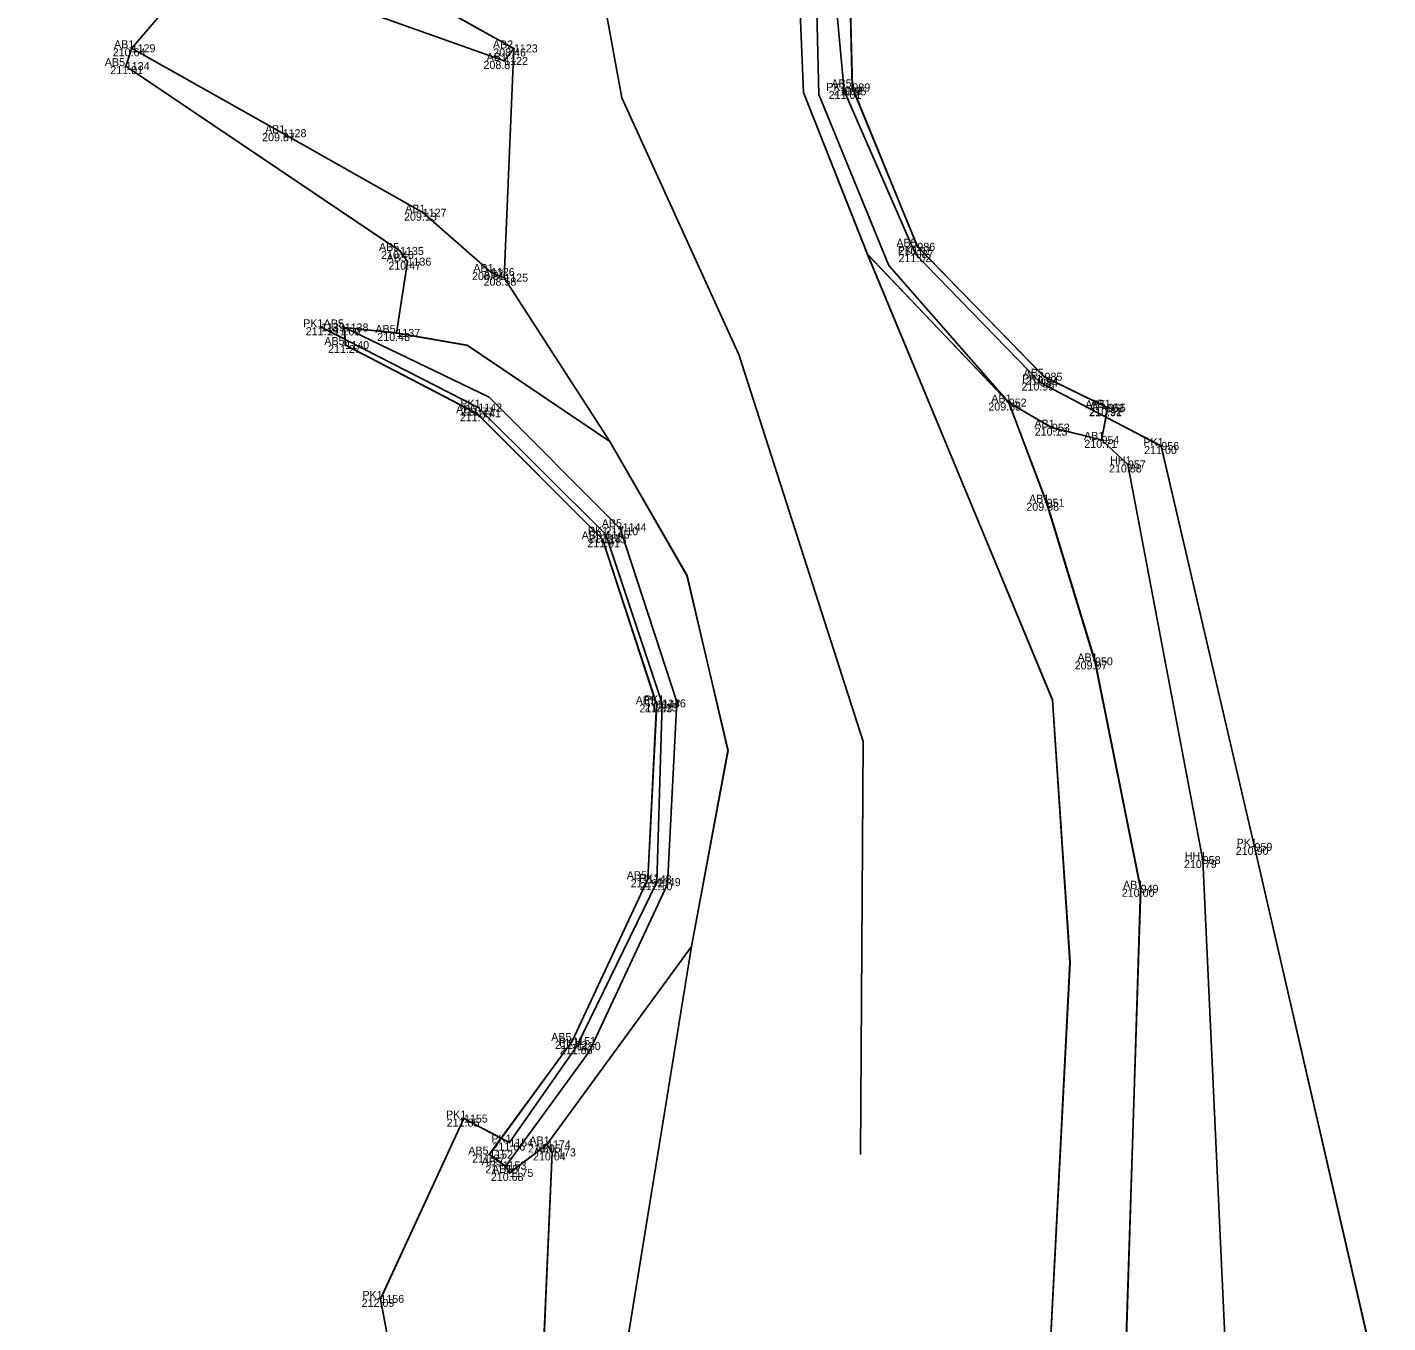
# Model space of a CAD drawing. Extents: x -262982 to -262706, y -1238714 to -1237093.
# Drawn here: x -262758.86 to -262724.86, y -1237246.95 to -1237214.58 of the extents above; entities that cross this region are included whole.
import ezdxf

# ---------------------------------------------------------------- set-up
doc = ezdxf.new("R2010")
doc.units = 0
for name, color, linetype in [('01_Hrana_betónu', 7, 'Continuous'), ('02_Oplotenie', 7, 'Continuous'), ('05_Hrana_terénu', 7, 'Continuous'), ('09_Múrik', 7, 'Continuous'), ('12_Prevzate', 7, 'Continuous'), ('Groma (21)', 7, 'Continuous'), ('Groma (22)', 7, 'Continuous'), ('Groma (23)', 7, 'Continuous'), ('Groma (24)', 7, 'Continuous'), ('U007_Betónové_dno', 7, 'Continuous'), ('U007_Betónový_múrik', 7, 'Continuous'), ('U007_Betóny_prídavné', 7, 'Continuous'), ('U007_Zeleň_vnútro', 7, 'Continuous')]:
    doc.layers.add(name, color=color, linetype=linetype)

msp = doc.modelspace()

# ---------------------------------------------------------------- linework, layer by layer
at = {"layer": '01_Hrana_betónu'}
msp.add_line((-262746.698, -1237215.108), (-262749.163, -1237213.734), dxfattribs=at)
for points in [[(-262756.251, -1237215.104), (-262752.477, -1237217.225), (-262748.975, -1237219.211), (-262747.271, -1237220.695), (-262746.938, -1237220.836), (-262746.698, -1237215.108), (-262746.941, -1237215.42), (-262750.811, -1237214.043), (-262751.454, -1237213.873), (-262753.276, -1237211.819), (-262753.562, -1237211.959)], [(-262734.328, -1237223.957), (-262733.383, -1237226.46), (-262732.174, -1237230.423), (-262731.033, -1237236.107), (-262731.406, -1237247.829), (-262731.217, -1237250.422), (-262730.427, -1237258.013), (-262730.707, -1237262.398)], [(-262745.779, -1237255.161), (-262745.901, -1237254.131), (-262746.066, -1237250.172), (-262745.744, -1237242.694), (-262745.872, -1237242.495), (-262746.806, -1237243.207), (-262746.909, -1237243.042)]]:
    msp.add_lwpolyline(points, dxfattribs=at)
at = {"layer": '02_Oplotenie'}
for points in [[(-262738.713, -1237213.277), (-262738.443, -1237216.169), (-262736.656, -1237220.248), (-262733.547, -1237223.456), (-262730.516, -1237225.043), (-262728.187, -1237235.058), (-262724.856, -1237249.517), (-262728.33, -1237250.897), (-262727.224, -1237257.246), (-262729.793, -1237261.019), (-262730.23, -1237281.105)], [(-262745.291, -1237290.168), (-262746.451, -1237287.071), (-262746.711, -1237279.427), (-262746.875, -1237275.982), (-262747.173, -1237269.439), (-262747.831, -1237258.131), (-262750.035, -1237246.355), (-262747.946, -1237241.849), (-262746.811, -1237242.447), (-262745.123, -1237240.039), (-262743.124, -1237235.94), (-262742.995, -1237231.474), (-262744.402, -1237227.257), (-262747.587, -1237224.08), (-262751.517, -1237222.073)]]:
    msp.add_lwpolyline(points, dxfattribs=at)
at = {"layer": '05_Hrana_terénu'}
msp.add_lwpolyline([(-262732.01, -1237224.888), (-262731.351, -1237225.503), (-262729.482, -1237235.388), (-262728.873, -1237248.563), (-262728.752, -1237252.453), (-262727.648, -1237257.282)], dxfattribs=at)
at = {"layer": '09_Múrik'}
for points in [[(-262732.01, -1237224.888), (-262733.251, -1237224.584), (-262734.328, -1237223.957), (-262737.33, -1237220.535), (-262739.076, -1237216.256), (-262739.151, -1237213.155), (-262738.631, -1237208.399), (-262738.385, -1237205.844), (-262736.697, -1237205.453), (-262737.25, -1237205.51), (-262738.513, -1237205.639)], [(-262732.01, -1237224.888), (-262731.851, -1237224.086), (-262733.435, -1237223.311), (-262736.613, -1237220.064), (-262738.238, -1237216.081), (-262738.308, -1237213.191), (-262737.794, -1237208.485), (-262737.605, -1237206.527), (-262736.507, -1237206.273), (-262736.697, -1237205.453)], [(-262750.927, -1237222.08), (-262749.634, -1237222.217), (-262749.356, -1237220.435), (-262749.544, -1237220.169), (-262756.398, -1237215.55)], [(-262746.909, -1237243.042), (-262744.809, -1237240.166), (-262742.858, -1237235.99), (-262742.624, -1237231.431), (-262744.042, -1237227.104), (-262747.319, -1237223.818), (-262750.927, -1237222.08)], [(-262746.909, -1237243.042), (-262747.313, -1237242.747), (-262745.241, -1237239.91), (-262743.352, -1237235.867), (-262743.128, -1237231.498), (-262744.48, -1237227.373), (-262747.618, -1237224.226), (-262750.911, -1237222.518), (-262750.927, -1237222.08)]]:
    msp.add_lwpolyline(points, dxfattribs=at)
at = {"layer": '12_Prevzate'}
for p, q in [((-262746.938, -1237220.836), (-262744.296, -1237224.926)), ((-262743.883, -1237247.547), (-262742.258, -1237237.55))]:
    msp.add_line(p, q, dxfattribs=at)
for points in [[(-262791.497, -1237120.005), (-262786.858, -1237124.868), (-262784.379, -1237126.547), (-262780.632, -1237128.447), (-262776.424, -1237129.031), (-262770.683, -1237129.062), (-262763.851, -1237132.452), (-262760.164, -1237141.037), (-262754.722, -1237164.802), (-262750.179, -1237185.786), (-262745.67, -1237207.188), (-262744.002, -1237216.34), (-262741.077, -1237222.757), (-262737.968, -1237232.423), (-262738.038, -1237242.742)], [(-262734.328, -1237223.957), (-262737.856, -1237220.253), (-262739.459, -1237216.209), (-262739.61, -1237212.605), (-262739.376, -1237209.427), (-262739.154, -1237207.455), (-262738.963, -1237206.444), (-262738.513, -1237205.639)], [(-262733.43, -1237250.203), (-262732.797, -1237237.943), (-262733.238, -1237231.387), (-262737.856, -1237220.253)], [(-262745.872, -1237242.495), (-262742.258, -1237237.55), (-262741.346, -1237232.652), (-262742.372, -1237228.278), (-262744.296, -1237224.926), (-262747.864, -1237222.526), (-262749.634, -1237222.217)]]:
    msp.add_lwpolyline(points, dxfattribs=at)
at = {"layer": 'Groma (21)'}
for centre in [(-262756.251, -1237215.104), (-262746.698, -1237215.108), (-262756.398, -1237215.55), (-262746.941, -1237215.42), (-262738.443, -1237216.169), (-262738.238, -1237216.081), (-262752.477, -1237217.225), (-262748.975, -1237219.211), (-262736.613, -1237220.064), (-262749.544, -1237220.169), (-262749.356, -1237220.435), (-262736.656, -1237220.248), (-262747.271, -1237220.695), (-262746.938, -1237220.836), (-262751.517, -1237222.073), (-262750.927, -1237222.08), (-262750.911, -1237222.518), (-262749.634, -1237222.217), (-262733.547, -1237223.456), (-262733.435, -1237223.311), (-262747.587, -1237224.08), (-262734.328, -1237223.957), (-262731.892, -1237224.099), (-262731.851, -1237224.086), (-262747.618, -1237224.226), (-262733.251, -1237224.584), (-262732.01, -1237224.888), (-262730.516, -1237225.043), (-262731.351, -1237225.503), (-262733.383, -1237226.46), (-262744.402, -1237227.257), (-262743.978, -1237227.072), (-262744.48, -1237227.373), (-262732.174, -1237230.423), (-262743.128, -1237231.498), (-262742.995, -1237231.474), (-262728.187, -1237235.058), (-262729.482, -1237235.388), (-262743.352, -1237235.867), (-262743.124, -1237235.94), (-262731.033, -1237236.107), (-262745.241, -1237239.91), (-262745.123, -1237240.039), (-262747.946, -1237241.849), (-262746.811, -1237242.447), (-262745.872, -1237242.495), (-262747.313, -1237242.747), (-262745.744, -1237242.694), (-262746.981, -1237243.018), (-262746.806, -1237243.207), (-262750.035, -1237246.355)]:
    msp.add_circle(centre, 0.01, dxfattribs=at)
at = {"layer": 'U007_Betónové_dno'}
msp.add_lwpolyline([(-262739.61, -1237212.61), (-262739.46, -1237216.21), (-262737.86, -1237220.25), (-262733.24, -1237231.39), (-262732.8, -1237237.94), (-262733.43, -1237250.2), (-262737.11, -1237251.76), (-262738.71, -1237251.34), (-262743.88, -1237247.55), (-262742.26, -1237237.55), (-262741.35, -1237232.65), (-262742.37, -1237228.28), (-262744.3, -1237224.93), (-262746.94, -1237220.84), (-262746.7, -1237215.11), (-262749.16, -1237213.73)], dxfattribs=at)
at = {"layer": 'U007_Betónový_múrik'}
for points in [[(-262737.86, -1237220.25), (-262739.46, -1237216.21), (-262739.61, -1237212.61), (-262739.38, -1237209.43), (-262739.15, -1237207.46), (-262738.96, -1237206.44), (-262738.51, -1237205.64), (-262737.25, -1237205.51), (-262736.7, -1237205.45), (-262736.51, -1237206.27), (-262737.61, -1237206.53), (-262737.79, -1237208.49), (-262738.31, -1237213.19), (-262738.24, -1237216.08), (-262736.61, -1237220.06), (-262733.44, -1237223.31), (-262731.85, -1237224.09), (-262732.01, -1237224.89), (-262733.25, -1237224.58), (-262734.33, -1237223.96)], [(-262746.81, -1237243.21), (-262746.91, -1237243.04), (-262747.31, -1237242.75), (-262745.24, -1237239.91), (-262743.35, -1237235.87), (-262743.13, -1237231.5), (-262744.48, -1237227.37), (-262747.62, -1237224.23), (-262750.91, -1237222.52), (-262750.93, -1237222.08), (-262749.63, -1237222.22), (-262747.86, -1237222.53), (-262744.3, -1237224.93), (-262742.37, -1237228.28), (-262741.35, -1237232.65), (-262742.26, -1237237.55), (-262745.87, -1237242.5)]]:
    msp.add_lwpolyline(points, close=True, dxfattribs=at)
at = {"layer": 'U007_Betóny_prídavné'}
for points in [[(-262755.22, -1237185.8), (-262749.16, -1237213.73), (-262746.7, -1237215.11), (-262746.94, -1237220.84), (-262744.3, -1237224.93), (-262747.86, -1237222.53), (-262749.63, -1237222.22), (-262749.36, -1237220.44), (-262749.54, -1237220.17), (-262756.4, -1237215.55), (-262756.25, -1237215.1), (-262753.56, -1237211.96), (-262753.28, -1237211.82), (-262751.45, -1237213.87), (-262750.81, -1237214.04), (-262751.86, -1237211.25), (-262755.01, -1237196.17), (-262759.85, -1237174.71), (-262764.43, -1237153.07), (-262766.66, -1237143.6), (-262767.82, -1237142.01), (-262766.6, -1237139.24), (-262764.4, -1237144.52), (-262759.45, -1237166.49)], [(-262731.03, -1237236.11), (-262731.41, -1237247.83), (-262731.22, -1237250.42), (-262730.43, -1237258.01), (-262730.71, -1237262.4), (-262732.38, -1237264.31), (-262732.87, -1237254.98), (-262733.43, -1237250.2), (-262732.8, -1237237.94), (-262733.24, -1237231.39), (-262737.86, -1237220.25), (-262734.33, -1237223.96), (-262733.38, -1237226.46), (-262732.17, -1237230.42)], [(-262742.26, -1237237.55), (-262743.88, -1237247.55), (-262744.04, -1237249.13), (-262744.27, -1237251.41), (-262744.52, -1237254.38), (-262744.61, -1237256.32), (-262745.78, -1237255.16), (-262745.9, -1237254.13), (-262746.07, -1237250.17), (-262745.74, -1237242.69), (-262745.87, -1237242.5)]]:
    msp.add_lwpolyline(points, close=True, dxfattribs=at)
at = {"layer": 'U007_Zeleň_vnútro'}
for points in [[(-262733.25, -1237224.58), (-262732.01, -1237224.89), (-262731.9, -1237224.32), (-262730.52, -1237225.04), (-262728.19, -1237235.06), (-262724.86, -1237249.52), (-262728.33, -1237250.9), (-262727.23, -1237257.19), (-262727.65, -1237257.28), (-262730.71, -1237262.4), (-262730.43, -1237258.01), (-262731.22, -1237250.42), (-262731.41, -1237247.83), (-262731.03, -1237236.11), (-262732.17, -1237230.42), (-262733.38, -1237226.46), (-262734.33, -1237223.96)], [(-262746.07, -1237250.17), (-262745.9, -1237254.13), (-262745.78, -1237255.16), (-262747.83, -1237258.13), (-262750.03, -1237246.36), (-262747.95, -1237241.85), (-262747.02, -1237242.34), (-262747.31, -1237242.75), (-262746.91, -1237243.04), (-262746.81, -1237243.21), (-262745.87, -1237242.5), (-262745.74, -1237242.69)]]:
    msp.add_lwpolyline(points, close=True, dxfattribs=at)

# ---------------------------------------------------------------- texts
at = {"layer": 'Groma (22)'}
for s, p in [('1129', (-262756.251, -1237215.204)), ('1123', (-262746.698, -1237215.208)), ('1122', (-262746.941, -1237215.52)), ('1134', (-262756.398, -1237215.65)), ('989', (-262738.238, -1237216.181)), ('988', (-262738.443, -1237216.269)), ('1128', (-262752.477, -1237217.325)), ('1127', (-262748.975, -1237219.311)), ('1135', (-262749.544, -1237220.269)), ('986', (-262736.613, -1237220.164)), ('1136', (-262749.356, -1237220.535)), ('987', (-262736.656, -1237220.348)), ('1126', (-262747.271, -1237220.795)), ('1125', (-262746.938, -1237220.936)), ('1139', (-262751.517, -1237222.173)), ('1138', (-262750.927, -1237222.18)), ('1137', (-262749.634, -1237222.317)), ('1140', (-262750.911, -1237222.618)), ('984', (-262733.547, -1237223.556)), ('985', (-262733.435, -1237223.411)), ('952', (-262734.328, -1237224.057)), ('1141', (-262747.618, -1237224.326)), ('1142', (-262747.587, -1237224.18)), ('983', (-262731.892, -1237224.199)), ('955', (-262731.851, -1237224.186)), ('953', (-262733.251, -1237224.684)), ('954', (-262732.01, -1237224.988)), ('956', (-262730.516, -1237225.143)), ('957', (-262731.351, -1237225.603)), ('951', (-262733.383, -1237226.56)), ('1143', (-262744.48, -1237227.473)), ('1145', (-262744.402, -1237227.357)), ('1144', (-262743.978, -1237227.172)), ('950', (-262732.174, -1237230.523)), ('1147', (-262743.128, -1237231.598)), ('1146', (-262742.995, -1237231.574)), ('959', (-262728.187, -1237235.158)), ('958', (-262729.482, -1237235.488)), ('1148', (-262743.352, -1237235.967)), ('1149', (-262743.124, -1237236.04)), ('949', (-262731.033, -1237236.207)), ('1151', (-262745.241, -1237240.01)), ('1150', (-262745.123, -1237240.139)), ('1155', (-262747.946, -1237241.949)), ('1154', (-262746.811, -1237242.547)), ('1174', (-262745.872, -1237242.595)), ('1152', (-262747.313, -1237242.847)), ('1153', (-262746.981, -1237243.118)), ('1173', (-262745.744, -1237242.794)), ('1175', (-262746.806, -1237243.307)), ('1156', (-262750.035, -1237246.455))]:
    msp.add_text(s, height=0.2, dxfattribs=at).set_placement(p)
at = {"layer": 'Groma (23)'}
for s, p in [('210.64', (-262756.724, -1237215.304)), ('208.46', (-262747.215, -1237215.308)), ('211.01', (-262756.785, -1237215.75)), ('208.87', (-262747.458, -1237215.62)), ('211.01', (-262738.83, -1237216.369)), ('210.95', (-262738.706, -1237216.281)), ('209.87', (-262752.99, -1237217.425)), ('209.13', (-262749.443, -1237219.411)), ('210.97', (-262737.082, -1237220.264)), ('210.46', (-262750.017, -1237220.369)), ('210.47', (-262749.835, -1237220.635)), ('211.02', (-262737.086, -1237220.448)), ('208.81', (-262747.744, -1237220.895)), ('208.58', (-262747.455, -1237221.036)), ('211.19', (-262751.9, -1237222.273)), ('211.09', (-262751.352, -1237222.28)), ('210.48', (-262750.112, -1237222.417)), ('211.27', (-262751.342, -1237222.718)), ('210.99', (-262734.011, -1237223.656)), ('210.94', (-262733.908, -1237223.511)), ('211.77', (-262748.019, -1237224.28)), ('209.85', (-262734.84, -1237224.157)), ('210.92', (-262732.319, -1237224.286)), ('210.91', (-262732.317, -1237224.299)), ('211.77', (-262748.05, -1237224.426)), ('210.13', (-262733.681, -1237224.784)), ('210.71', (-262732.441, -1237225.088)), ('211.00', (-262730.945, -1237225.243)), ('210.88', (-262731.824, -1237225.703)), ('209.98', (-262733.89, -1237226.66)), ('212.13', (-262744.833, -1237227.457)), ('212.10', (-262744.408, -1237227.272)), ('211.91', (-262744.863, -1237227.573)), ('209.97', (-262732.682, -1237230.623)), ('211.83', (-262743.559, -1237231.698)), ('212.13', (-262743.426, -1237231.674)), ('210.90', (-262728.655, -1237235.258)), ('210.79', (-262729.951, -1237235.588)), ('211.92', (-262743.778, -1237236.067)), ('212.10', (-262743.554, -1237236.14)), ('210.00', (-262731.505, -1237236.307)), ('211.72', (-262745.672, -1237240.11)), ('211.86', (-262745.549, -1237240.239)), ('211.85', (-262748.377, -1237242.049)), ('211.66', (-262747.232, -1237242.647)), ('210.05', (-262746.344, -1237242.695)), ('211.67', (-262747.74, -1237242.947)), ('210.04', (-262746.221, -1237242.894)), ('211.55', (-262747.412, -1237243.218)), ('210.68', (-262747.274, -1237243.407)), ('212.09', (-262750.503, -1237246.555))]:
    msp.add_text(s, height=0.2, dxfattribs=at).set_placement(p)
at = {"layer": 'Groma (24)'}
for s, p in [('AB1', (-262756.689, -1237215.104)), ('AB2', (-262747.222, -1237215.108)), ('AB5', (-262756.922, -1237215.55)), ('AB1', (-262747.379, -1237215.42)), ('PK1', (-262738.89, -1237216.169)), ('AB5', (-262738.762, -1237216.081)), ('AB1', (-262752.915, -1237217.225)), ('AB1', (-262749.413, -1237219.211)), ('AB5', (-262750.068, -1237220.169)), ('AB5', (-262737.137, -1237220.064)), ('PK1', (-262737.103, -1237220.248)), ('AB5', (-262749.88, -1237220.435)), ('AB1', (-262747.709, -1237220.695)), ('AB2', (-262747.462, -1237220.836)), ('PK1', (-262751.964, -1237222.073)), ('AB5', (-262751.451, -1237222.08)), ('AB5', (-262750.158, -1237222.217)), ('AB5', (-262751.435, -1237222.518)), ('AB5', (-262733.959, -1237223.311)), ('PK1', (-262733.994, -1237223.456)), ('AB1', (-262734.766, -1237223.957)), ('AB5', (-262748.142, -1237224.226)), ('PK1', (-262748.034, -1237224.08)), ('AB5', (-262732.416, -1237224.099)), ('AB1', (-262732.289, -1237224.086)), ('AB1', (-262733.689, -1237224.584)), ('AB1', (-262732.448, -1237224.888)), ('PK1', (-262730.963, -1237225.043)), ('HH1', (-262731.798, -1237225.503)), ('AB1', (-262733.821, -1237226.46)), ('AB5', (-262744.502, -1237227.072)), ('AB5', (-262745.004, -1237227.373)), ('PK1', (-262744.849, -1237227.257)), ('AB1', (-262732.612, -1237230.423)), ('AB5', (-262743.652, -1237231.498)), ('PK1', (-262743.442, -1237231.474)), ('PK1', (-262728.634, -1237235.058)), ('HH1', (-262729.929, -1237235.388)), ('AB5', (-262743.876, -1237235.867)), ('PK1', (-262743.571, -1237235.94)), ('AB1', (-262731.471, -1237236.107)), ('AB5', (-262745.765, -1237239.91)), ('PK1', (-262745.57, -1237240.039)), ('PK1', (-262748.393, -1237241.849)), ('AB5', (-262747.837, -1237242.747)), ('PK1', (-262747.258, -1237242.447)), ('AB1', (-262746.31, -1237242.495)), ('AB1', (-262746.182, -1237242.694)), ('AB5', (-262747.505, -1237243.018)), ('AB1', (-262747.244, -1237243.207)), ('PK1', (-262750.482, -1237246.355))]:
    msp.add_text(s, height=0.2, dxfattribs=at).set_placement(p)

doc.saveas('drawing.dxf')
